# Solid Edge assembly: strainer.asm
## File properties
Author: rkriggs
Template: Sync Iso Assembly.asm
Last saved by: plm
Revision: 24
Application: Solid Edge
major_rev: A
圖檔名稱: strainer
圖檔編號: strainer
generation: 2
id: A72C82FEC8684065A34F85279875D523
classification: Mechanical/Assembly
thumbnail: vault:///?fileId=471A3A905E4041318A2E64E941D8C8D9
authoring_tool: Solid Edge
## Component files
Strainer Body.par
Strainer Top.par
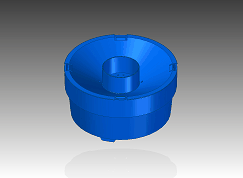
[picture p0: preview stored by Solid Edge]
